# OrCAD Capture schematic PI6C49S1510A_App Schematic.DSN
size Custom; title: PI6C49S1510A Application Circuit; rev: 1.0; note: Diodes Inc. Clock IC Application Engineering
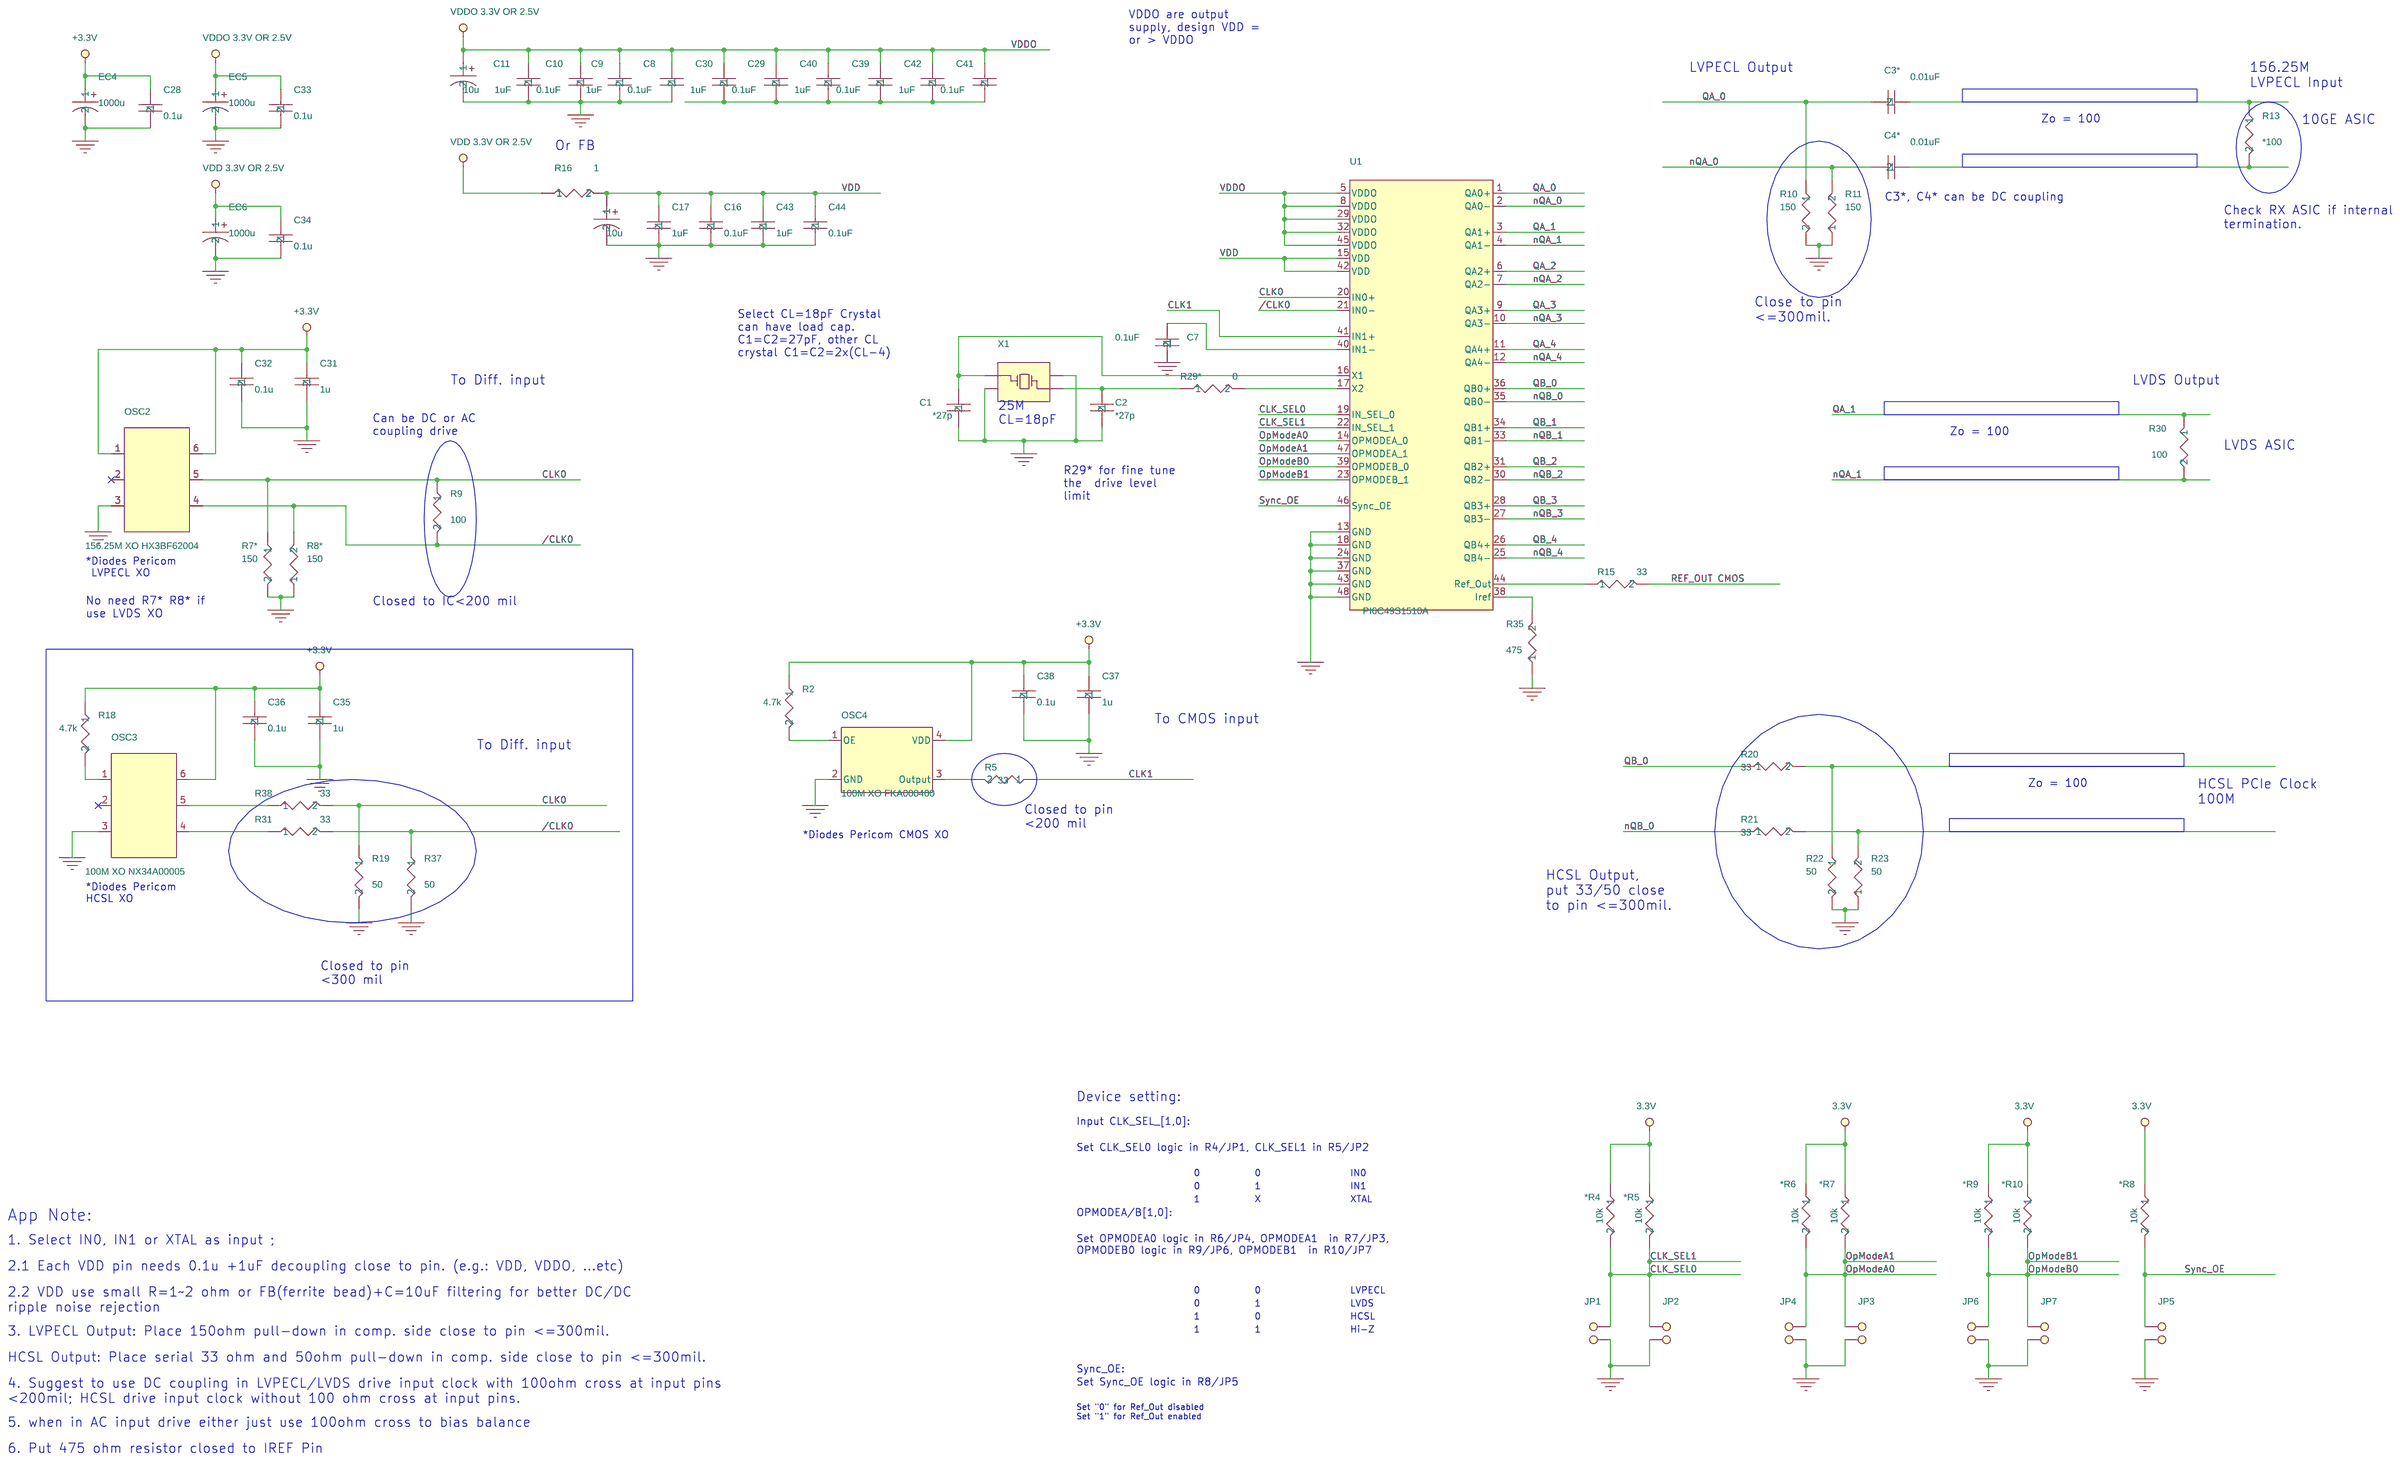
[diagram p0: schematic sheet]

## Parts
*R4  10k  [R_0402]
*R5  10k  [R_0402]
*R6  10k  [R_0402]
*R7  10k  [R_0402]
*R8  10k  [R_0402]
*R9  10k  [R_0402]
*R10  10k  [R_0402]
C1  *27p  [CC_0402]
C2  *27p  [CC_0402]
C3*  0.01uF  [CC_0402]
C4*  0.01uF  [CC_0402]
C7  0.1uF  [CC_0402]
C8  0.1uF  [CC_0402]
C9  1uF  [CC_0402]
C10  0.1uF  [CC_0402]
C11  1uF  [CC_0402]
C16  0.1uF  [CC_0402]
C17  1uF  [CC_0402]
C28  0.1u  [CC_0402]
C29  0.1uF  [CC_0402]
C30  1uF  [CC_0402]
C31  1u  [CC_0402]
C32  0.1u  [CC_0402]
C33  0.1u  [CC_0402]
C34  0.1u  [CC_0402]
C35  1u  [CC_0402]
C36  0.1u  [CC_0402]
C37  1u  [CC_0402]
C38  0.1u  [CC_0402]
C39  0.1uF  [CC_0402]
C40  1uF  [CC_0402]
C41  0.1uF  [CC_0402]
C42  1uF  [CC_0402]
C43  1uF  [CC_0402]
C44  0.1uF  [CC_0402]
EC1  10u  [CAP1000UF]
EC3  10u  [CAP1000UF]
EC4  1000u  [CAP1000UF]
EC5  1000u  [CAP1000UF]
EC6  1000u  [CAP1000UF]
JP1  2PIN HEADER  [SIP\2P]
JP2  2PIN HEADER  [SIP\2P]
JP3  2PIN HEADER  [SIP\2P]
JP4  2PIN HEADER  [SIP\2P]
JP5  2PIN HEADER  [SIP\2P]
JP6  2PIN HEADER  [SIP\2P]
JP7  2PIN HEADER  [SIP\2P]
OSC2  156.25M XO HX3BF62004  [XO 5X7]
OSC3  100M XO NX34A00005  [XO 5X7]
OSC4  100M XO FKA000400  [CYRSTAL-3_2X2_5MM]
R2  4.7k  [R_0402]
R5  33  [R_0402]
R7*  150  [R_0402]
R8*  150  [R_0402]
R9  100  [R_0402]
R10  150  [R_0402]
R11  150  [R_0402]
R13  *100  [R_0402]
R15  33  [R_0402]
R16  1  [R_0402]
R18  4.7k  [R_0402]
R19  50  [R_0402]
R20  33  [R_0402]
R21  33  [R_0402]
R22  50  [R_0402]
R23  50  [R_0402]
R29*  0  [R_0402]
R30  100  [R_0402]
R31  33  [R_0402]
R35  475  [R_0402]
R37  50  [R_0402]
R38  33  [R_0402]
U1  PI6C49S1510A  [TQFN48]
X1  Crystal_4P_SMD  [CYRSTAL@SM4]

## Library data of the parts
*R4 = R_0402_18
*R5 = R_0402_11
*R6 = R_0402_14
*R7 = R_0402_13
*R8 = R_0402_17
*R9 = R_0402_28
*R10 = R_0402_25
C1 = C_0.1u_0402_2
C2 = C_0.1u_0402_4
C3* = C_10n_0402_4
C4* = C_10n_0402_13
C7 = C_10n_0402_3
C8 = C_10n_0402_16
C9 = C_10n_0402_15
C10 = C_10n_0402_14
C11 = C_10n_0402_6
C16 = C_10n_0402
C17 = C_10n_0402_1
C28 = C_0.1u_0402_3
C29 = C_10n_0402_7
C30 = C_10n_0402_12
C31 = C_0.1u_0402_9
C32 = C_0.1u_0402_7
C33 = C_0.1u_0402_5
C34 = C_0.1u_0402
C35 = C_0.1u_0402_8
C36 = C_0.1u_0402_1
C37 = C_0.1u_0402_6
C38 = C_0.1u_0402_10
C39 = C_10n_0402_10
C40 = C_10n_0402_8
C41 = C_10n_0402_11
C42 = C_10n_0402_9
C43 = C_10n_0402_5
C44 = C_10n_0402_2
EC1 = C_alum_1000u_2
EC3 = C_alum_1000u_4
EC4 = C_alum_1000u_1
EC5 = C_alum_1000u_3
EC6 = C_alum_1000u
JP1-JP7 = 2PIN_HEADER
OSC2 OSC3 = XO_5X7
OSC4 = UX3AA00003_0
R2 = R_0402_16
R5 = R_0402_3
R7* = R_0402
R8* = R_0402_20
R9 = R_0402_26
R10 = R_0402_9
R11 = R_0402_10
R13 = R_0402_6
R15 = R_0402_2
R16 = R_0402_22
R18 = R_0402_24
R19 = R_0402_23
R20 = R_0402_12
R21 = R_0402_8
R22 = R_0402_7
R23 = R_0402_4
R29* = R_0402_1
R30 = R_0402_21
R31 = R_0402_19
R35 = R_0402_27
R37 = R_0402_5
R38 = R_0402_15
U1 = PI6C49S1510ZDE@TQFN48_7
X1 = Crystal_4P_SMD

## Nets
3.3V: *R4.1 *R5.1 *R6.1 *R7.1 *R8.1 *R9.1 *R10.1
+3.3V: C28.1 C31.1 C32.1 C35.1 C36.1 C37.1 C38.1 EC4.1 OSC2.1 OSC2.6 OSC3.6 OSC4.4(VDD) R2.1 R18.1
GND: C1.2 C2.2 C7.2 C8.2 C9.2 C10.2 C11.2 C16.2 C17.2 C28.2 C31.2 C32.2 C33.2 C34.2 C35.2 C36.2 C37.2 C38.2 C43.2 C44.2 EC1.2 EC3.2 EC4.2 EC5.2 EC6.2 JP1.1 JP2.1 JP3.1 JP4.1 JP5.1 JP6.1 JP7.1 OSC2.3 OSC3.3 OSC4.2(GND) R7*.1 R8*.2 R10.1 R11.2 R19.2 R22.1 R23.2 R35.1 R37.2 U1.13(GND) U1.18(GND) U1.24(GND) U1.37(GND) U1.43(GND) U1.48(GND) X1.2 X1.4
VDD: C16.1 C17.1 C43.1 C44.1 EC1.1 R16.2 U1.15(VDD) U1.42(VDD)
VDD 3.3V or 2.5V: C34.1 EC6.1 R16.1
VDDO 3.3V or 2.5V: C8.1 C9.1 C10.1 C11.1 C29.1 C30.1 C33.1 C39.1 C40.1 C41.1 C42.1 EC3.1 EC5.1 U1.5(VDDO) U1.8(VDDO) U1.29(VDDO) U1.32(VDDO) U1.45(VDDO)
/CLK0: OSC2.4 R7*.2 R9.2 R31.2 R37.1 U1.21(IN0-)
CLK0: OSC2.5 R8*.1 R9.1 R19.1 R38.2 U1.20(IN0+)
CLK1: R5.1 U1.41(IN1+)
CLK_SEL0: *R4.2 JP1.2 U1.19(IN_SEL_0)
CLK_SEL1: *R5.2 JP2.2 U1.22(IN_SEL_1)
nQA_0: C4*.2 R10.2 U1.2(QA0-)
nQA_1: R30.2 U1.4(QA1-)
nQA_2: U1.7(QA2-)
nQA_3: U1.10(QA3-)
nQA_4: U1.12(QA4-)
nQB_0: R21.1 U1.35(QB0-)
nQB_1: U1.33(QB1-)
nQB_2: U1.30(QB2-)
nQB_3: U1.27(QB3-)
nQB_4: U1.25(QB4-)
OpModeA0: *R6.2 JP4.2 U1.14(OPMODEA_0)
OpModeA1: *R7.2 JP3.2 U1.47(OPMODEA_1)
OpModeB0: *R9.2 JP6.2 U1.39(OPMODEB_0)
OpModeB1: *R10.2 JP7.2 U1.23(OPMODEB_1)
QA_0: C3*.2 R11.1 U1.1(QA0+)
QA_1: R30.1 U1.3(QA1+)
QA_2: U1.6(QA2+)
QA_3: U1.9(QA3+)
QA_4: U1.11(QA4+)
QB_0: R20.1 U1.36(QB0+)
QB_1: U1.34(QB1+)
QB_2: U1.31(QB2+)
QB_3: U1.28(QB3+)
QB_4: U1.26(QB4+)
REF_OUT CMOS: R15.2
Sync_OE: *R8.2 JP5.2 U1.46(Sync_OE)
N3706733: R20.2 R23.1
N3706737: R21.2 R22.2
N3707123: C3*.1 R13.1
N3707137: C4*.1 R13.2
N4641079: C1.1 U1.16(X1) X1.3
N4641083: C2.1 R29*.1 X1.1
N4641596: R29*.2 U1.17(X2)
N4643273: C29.2 C30.2 C39.2 C40.2 C41.2 C42.2
N4645856: OSC3.1 R18.2
N4645932: OSC3.5 R38.1
N4645962: OSC3.4 R31.1
N4646911: C7.1 U1.40(IN1-)
N4647386: OSC4.1(OE) R2.2
N4647410: OSC4.3(Output) R5.2
N4655551: R15.1 U1.44(Ref_Out)
N4655746: R35.2 U1.38(Iref)

Not connected (* = marked no-connect by the designer): OSC2 2*; OSC3 2*

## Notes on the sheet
- VDDO are output
  supply, design VDD =
  or > VDDO
- LVPECL Output
- 156.25M
  LVPECL Input
- Zo = 100
- 10GE ASIC
- Or FB
- C3*, C4* can be DC coupling
- Check RX ASIC if internal
  termination.
- Close to pin
  <=300mil.
- Select CL=18pF Crystal
  can have load cap.
  C1=C2=27pF, other CL
  crystal C1=C2=2x(CL-4)
- To Diff. input
- LVDS Output
- 25M
  CL=18pF
- Can be DC or AC
  coupling drive
- Zo = 100
- LVDS ASIC
- R29* for fine tune
  the  drive level
  limit
- *Diodes Pericom
   LVPECL XO
- No need R7* R8* if
  use LVDS XO
- Closed to IC<200 mil
- To CMOS input
- To Diff. input
- Zo = 100
- HCSL PCIe Clock
  100M
- Closed to pin
  <200 mil
- *Diodes Pericom CMOS XO
- HCSL Output,
  put 33/50 close
  to pin <=300mil.
- *Diodes Pericom
  HCSL XO
- Closed to pin
  <300 mil
- Device setting:
- Input CLK_SEL_[1,0]:
- Set CLK_SEL0 logic in R4/JP1, CLK_SEL1 in R5/JP2
- 0           0
- IN0
- 0           1
- IN1
- 1           X
- XTAL
- App Note:
- OPMODEA/B[1,0]:
- 1. Select IN0, IN1 or XTAL as input ;
- Set OPMODEA0 logic in R6/JP4, OPMODEA1  in R7/JP3,
  OPMODEB0 logic in R9/JP6, OPMODEB1  in R10/JP7
- 2.1 Each VDD pin needs 0.1u +1uF decoupling close to pin. (e.g.: VDD, VDDO, ...etc)
- 2.2 VDD use small R=1~2 ohm or FB(ferrite bead)+C=10uF filtering for better DC/DC
  ripple noise rejection
- 0           0
- LVPECL
- 0           1
- LVDS
- 1           0
- HCSL
- 3. LVPECL Output: Place 150ohm pull-down in comp. side close to pin <=300mil.
- 1           1
- Hi-Z
- HCSL Output: Place serial 33 ohm and 50ohm pull-down in comp. side close to pin <=300mil.
- Sync_OE:
- 4. Suggest to use DC coupling in LVPECL/LVDS drive input clock with 100ohm cross at input pins
  <200mil; HCSL drive input clock without 100 ohm cross at input pins.
- Set Sync_OE logic in R8/JP5
- Set "0" for Ref_Out disabled
  Set "1" for Ref_Out enabled
- 5. when in AC input drive either just use 100ohm cross to bias balance
- 6. Put 475 ohm resistor closed to IREF Pin
